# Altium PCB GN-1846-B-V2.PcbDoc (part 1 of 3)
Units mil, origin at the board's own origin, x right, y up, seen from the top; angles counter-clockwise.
Board outline 11621.85 x 2979.29 mil, 2 copper layers (Top, Bottom), stack 12.7 mil thick; 356 components, 252 nets, 1224 pads, 826 vias.
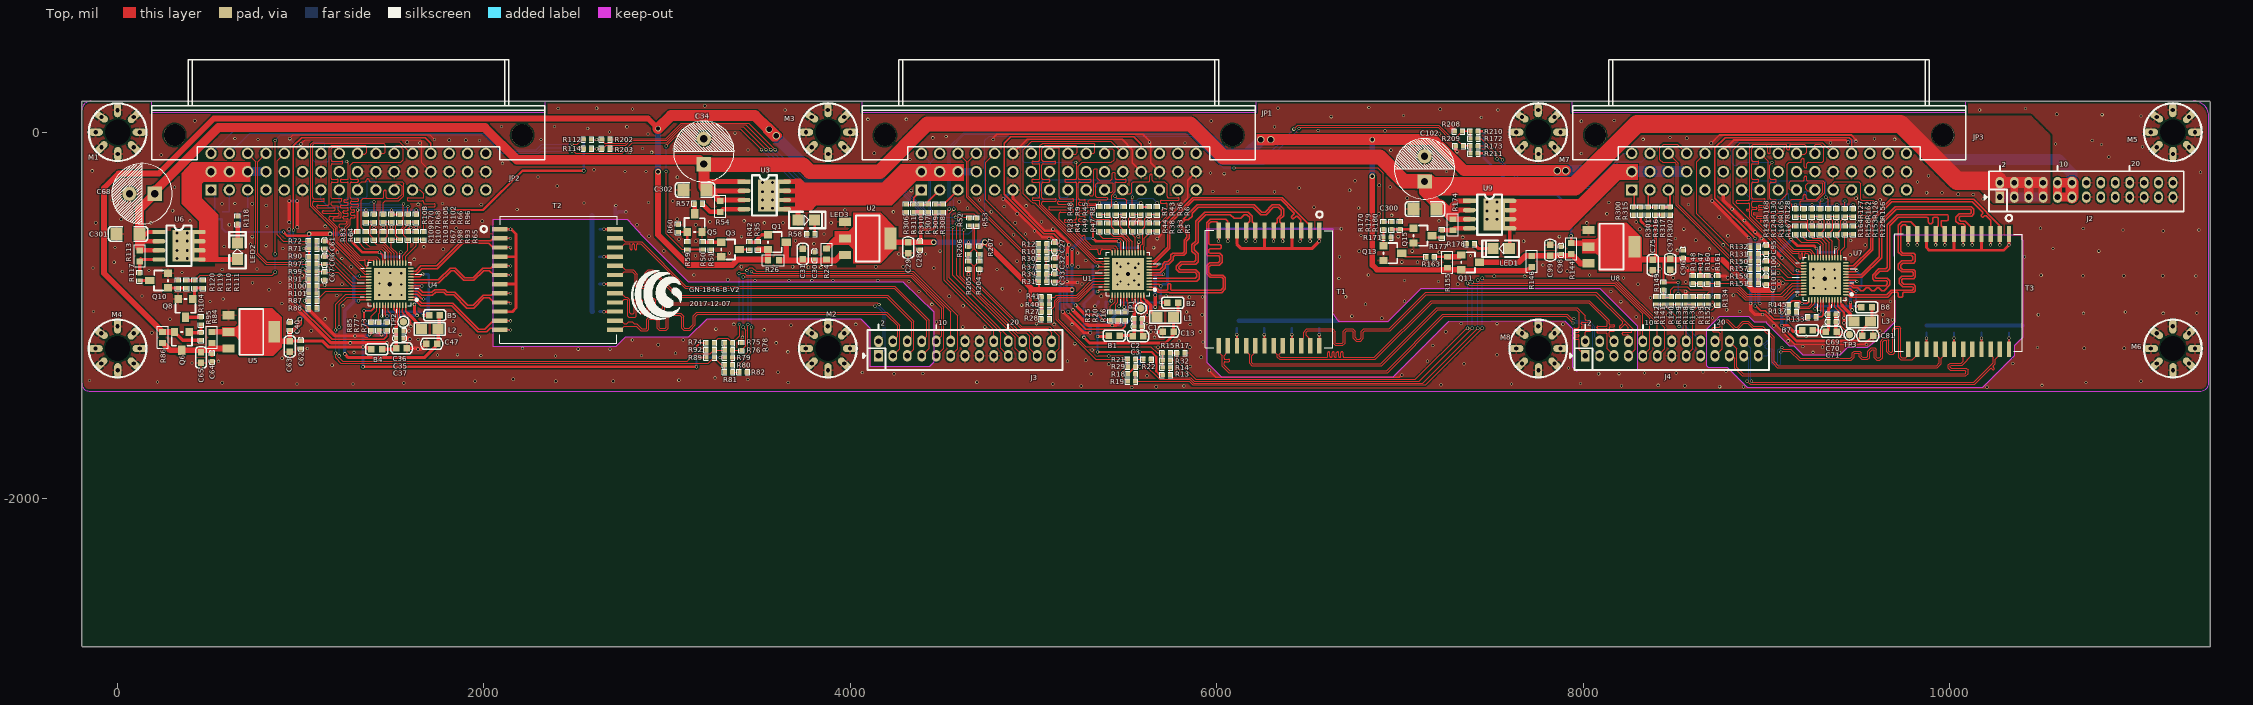
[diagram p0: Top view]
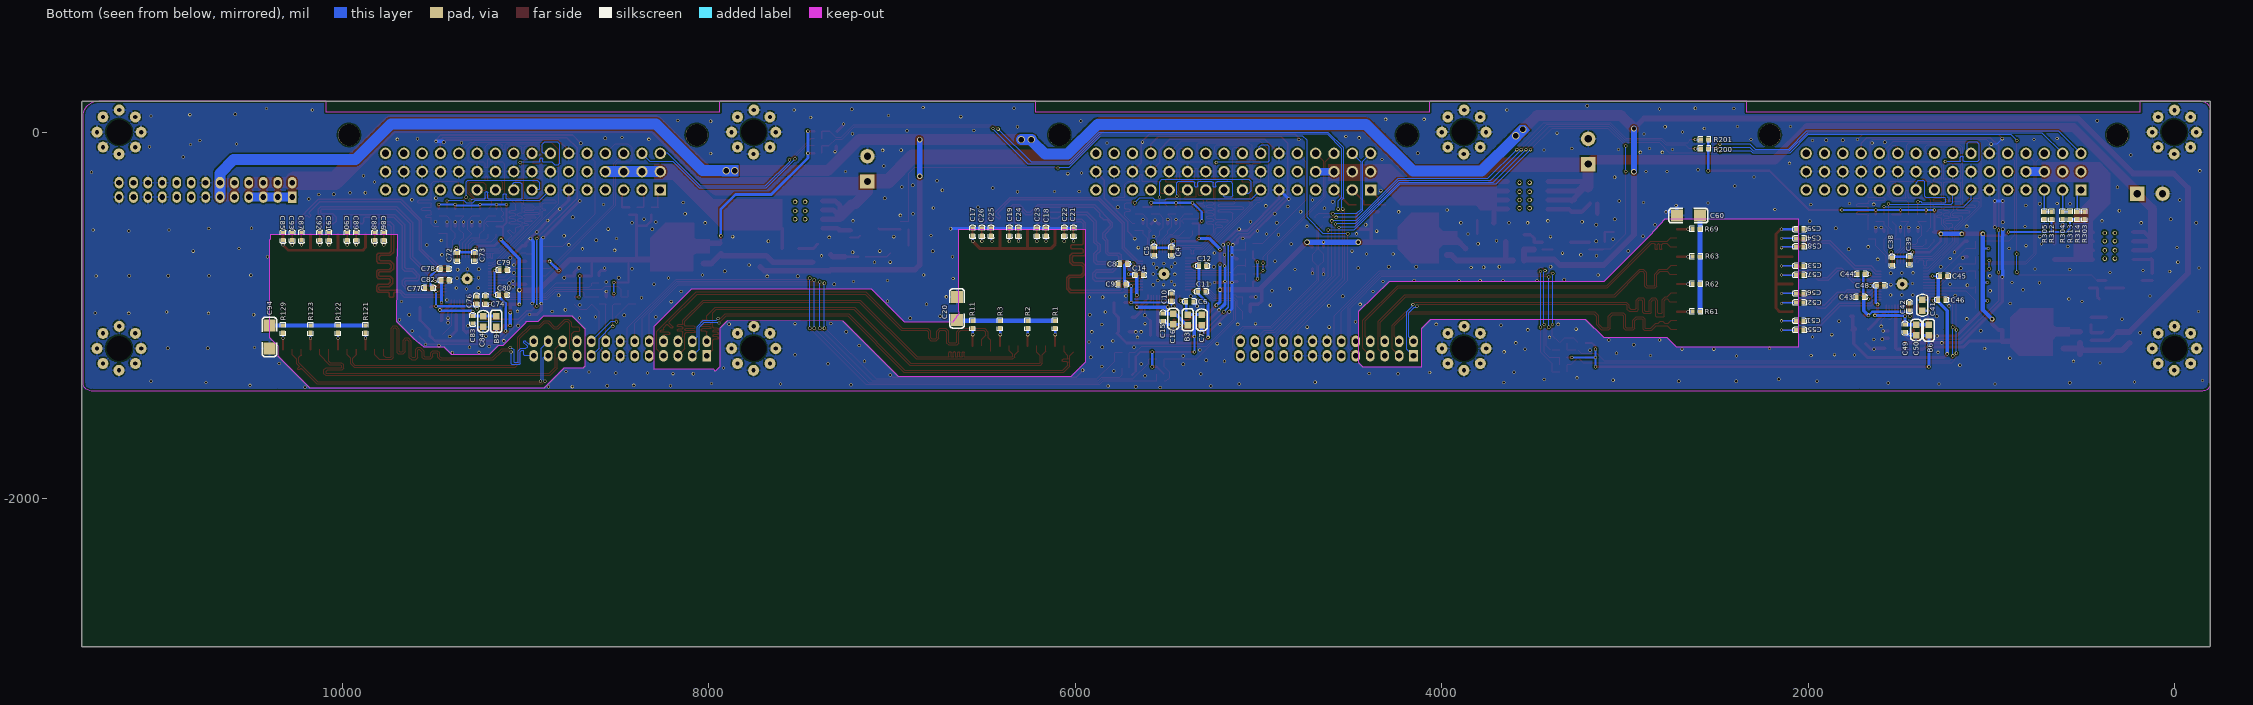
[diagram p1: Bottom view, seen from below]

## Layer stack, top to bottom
Top: signal copper 1.35
Dielectric: dielectric 10, FR-4, Dk 4.3
Bottom: signal copper 1.35

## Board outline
-196.85,167.44 -195,169.29 185,169.29 11420.71,169.29 11425,165 11425,65 11425,-2805 11425,-2810 -190.41,-2810 -196.85,-2803.55 -196.85,-2775 -196.85,167.44

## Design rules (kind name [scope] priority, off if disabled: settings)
Clearance "'Default' PADS rule_18" [All] p1: gap=5
ComponentClearance "'Default' PADS rule_12" [All] p1: gap=0 collisioncheckmode=3 verticalgap=0 showdistances=FALSE
FlightTimeFalling "'Default' PADS rule_10" [All] p1: maximum=10.00
FlightTimeRising "'Default' PADS rule_9" [All] p1: maximum=10.00
Length "'Default' PADS rule_5" [All] p1: maxlimit=50000 minlimit=0
MaxMinImpedance "'Default' PADS rule_8" [All] p1: minimum=50.00 maximum=150.0
MinimumSolderMaskSliver [All] p1: minsoldermaskwidth=0
PlaneClearance "'Default' PADS rule_14" [All] p1: clearance=5
PlaneConnect "Power Plane Connect Style - pads with no thermal_19" [(Name='U7-49')] p1: planeconnectstyle=NoConnect reliefexpansion=20 reliefentries=4 reliefconductorwidth=10 reliefairgap=10 // PAD - No Thermal Connect Rule
PlaneConnect "Power Plane Connect Style - pads with no thermal" [(Name='JP1-A14') Or (Name='JP1-A15') Or (Name='JP1-A16') Or (Name='JP1-B5') Or (Name='JP1-B6') Or (Name='JP1-C1') Or (Name='JP1-C2') Or (Name='JP1-C3') Or (Name='JP1-C4') Or (Name='JP1-C5') Or (Name='JP1-C13') Or (Name='JP1-C14') Or (Name='JP1-C15') Or (Name='JP1-C16') Or (Name='JP1-0') Or (Name='JP1-0/2') Or (Name='JP2-A14') Or (Name='JP2-A15') Or (Name='JP2-A16') Or (Name='JP2-B5') Or (Name='JP2-B6') Or (Name='JP2-C1') Or (Name='JP2-C2') Or (Name='JP2-C3') Or (Name='JP2-C4') Or (Name='JP2-C5') Or (Name='JP2-C13') Or (Name='JP2-C14') Or (Name='JP2-C15') Or (Name='JP2-C16') Or (Name='JP2-0') Or (Name='JP2-0/2') Or (Name='JP3-A14') Or (Name='JP3-A15') Or (Name='JP3-A16') Or (Name='JP3-B5') Or (Name='JP3-B6') Or (Name='JP3-C1') Or (Name='JP3-C2') Or (Name='JP3-C3') Or (Name='JP3-C4') Or (Name='JP3-C5') Or (Name='JP3-C13') Or (Name='JP3-C14') Or (Name='JP3-C15') Or (Name='JP3-C16') Or (Name='JP3-0') Or (Name='JP3-0/2') Or (Name='U1-49') Or (Name='U4-49')] p2: planeconnectstyle=NoConnect reliefexpansion=20 reliefentries=4 reliefconductorwidth=10 reliefairgap=10 // PAD - No Thermal Connect Rule
PlaneConnect "Power Plane Connect Style - from global settings" [All] p3: planeconnectstyle=Relief reliefexpansion=20 reliefentries=4 reliefconductorwidth=15 reliefairgap=10
PolygonConnect PolygonConnect_1 [All vs isvia] p1: connectstyle=Direct reliefconductorwidth=10 reliefentries=4 polygonreliefangle="90 Angle"
PolygonConnect [All] p2: connectstyle=Relief reliefconductorwidth=10 reliefentries=4 polygonreliefangle="90 Angle"
RoutingLayers "'Default' PADS rule_3" [All] p1: top layer_v5=TRUE bottom layer_v5=TRUE
RoutingPriority "'Default' PADS rule_2" [All] p1: routingpriority=3
RoutingTopology "'Default' PADS rule" [All] p1: topology=Shortest
RoutingVias "'Default' PADS rule_4" [All] p1: holewidth=12 width=18 viastyle="Through Hole" minholewidth=12 minwidth=18 maxholewidth=12 maxwidth=18
SMDToCorner "'Default' PADS rule_16" [All] p1: distance=0
SMDToPlane "'Default' PADS rule_17" [All] p1: distance=50000
SilkToSilkClearance [All] p1: silktosilkclearance=0
SilkscreenOverComponentPads [All] p1: minsilkscreentomaskgap=0
SolderMaskExpansion [All] p1: expansion=5
TestPointUsage FabricationTestPointUsage [All] p1: valid=0 allowmultiple=FALSE
Testpoint FabricationTestpoint [All] p1: side=3 testpointundercomponent=TRUE minsize=40 maxsize=100 preferedsize=60 minholesize=0 maxholesize=40 preferedholesize=32 testpointgrid=1 style=297 order=0123456789
Width "'Default' PADS rule_13" [All] p1: maxlimit=100 minlimit=5 preferedwidth=8
15 further rules are at their usual default settings.

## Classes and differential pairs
component class "P02 Block": M1 M2 M3 M4 M5 M6 M7 M8
component class "P05 PHY 3": B7 B8 B9 C69 C70 C71 C72 C73 C74 C75 C76 C77 C78 C79 C80 C81 C82 C83 C84 C85 C86 C87 C88 C89 C90 C91 C92 C93 C94 C95 C96 C97 C98 C99 C100 C101 C102 c300 JP3 L3 LED1 Q11 Q13 Q15 R121 R122 R123 R124 R125 R126 R127 R128 R129 R130 R131 R132 R133 R134 R135 R136 R137 R138 R139 R140 R141 R142 R143 R144 R145 R146 R147 R148 R149 R150 R151 R152 R153 R155 R156 R157 R158 R159 R160 R161 R162 R163 R164 R165 R167 R168 R169 R170 R171 R172 R173 R174 R177 R178 R179 R180 R208 R209 R210 R211 R300 R301 R302 R315 R316 R317 T3 TP3 U7 U8 U9
component class "P04 PHY 2": B4 B5 B6 C35 C36 C37 C38 C39 C40 C41 C42 C43 C44 C45 C46 C47 C48 C49 C50 C51 C52 C53 C54 C55 C56 C57 C58 C59 C60 C61 C62 C63 C64 C65 C66 C67 C68 c301 JP2 L2 LED2 Q6 Q8 Q10 R61 R62 R63 R64 R65 R66 R67 R68 R69 R70 R71 R72 R73 R74 R75 R76 R77 R78 R79 R80 R81 R82 R83 R84 R85 R86 R87 R88 R89 R90 R91 R92 R93 R95 R96 R97 R98 R99 R100 R101 R102 R103 R104 R105 R107 R108 R109 R110 R111 R112 R113 R114 R117 R118 R119 R120 R200 R201 R202 R203 R303 R304 R305 R312 R313 R314 T2 TP2 U4 U5 U6
component class "P03 PHY 1": B1 B2 B3 C1 C2 C3 C4 C5 C6 C7 C8 C9 C10 C11 C12 C13 C14 C15 C16 C17 C18 C19 C20 C21 C22 C23 C24 C25 C26 C27 C28 C29 C30 C31 C32 C33 C34 c302 JP1 L1 LED3 Q1 Q3 Q5 R1 R2 R3 R4 R5 R6 R7 R8 R9 R10 R11 R12 R13 R14 R15 R16 R17 R18 R19 R20 R21 R22 R23 R24 R25 R26 R27 R28 R29 R30 R31 R32 R33 R35 R36 R37 R38 R39 R40 R41 R42 R43 R44 R45 R47 R48 R49 R50 R51 R52 R53 R54 R57 R58 R59 R60 R204 R205 R206 R207 R306 R307 R308 R309 R310 R311 T1 TP1 U1 U2 U3
component class "P06 CONNECT & LED": J2 J3 J4

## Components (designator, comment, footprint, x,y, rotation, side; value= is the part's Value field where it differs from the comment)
B1 "MGLB1608M600T3R0-LF" L0603 5440,-1110 r270 top
B2 "MGLB1608M600T3R0-LF" L0603 5760,-930 r90 top
B3 "MGLB1608M600T3R0-LF" L0603 5385,-1025 r0 bottom
B4 "MGLB1608M600T3R0-LF" L0603 1415,-1185 r270 top
B5 "MGLB1608M600T3R0-LF" L0603 1730,-1000 r90 top
B6 "MGLB1608M600T3R0-LF" L0603 1340,-1080 r180 bottom
B7 "MGLB1608M600T3R0-LF" L0603 9225,-1080 r270 top
B8 "MGLB1608M600T3R0-LF" L0603 9548,-956 r90 top
B9 "MGLB1608M600T3R0-LF" L0603 9161,-1033 r180 bottom
C1 "0.1uF" 0402C 5550.47,-1020 r0 top
C2 "0.1uF" 0402C 5550.47,-1060 r0 top
C3 "10uF" C0603 5570,-1115 r0 top
C4 "0.1uF" 0402C 5475,-630.47 r270 bottom
C5 "0.1uF" 0402C 5570,-630 r270 bottom
C6 "0.1uF" 0402C 5395,-925 r180 bottom
C7 "10uF" C0603 5310,-1025 r270 bottom
C8 "0.1uF" 0402C 5716.74,-718.26 r0 bottom
C9 "0.1uF" 0402C 5725,-830 r0 bottom
C10 "0.1uF" 0402C 5475,-920 r90 bottom
C11 "0.1uF" 0402C 5330,-870 r180 bottom
C12 "0.1uF" 0402C 5325,-730 r180 bottom
C13 "10uF" C0603 5735,-1090 r180 top
C14 "0.1uF" 0402C 5670,-780 r180 bottom
C15 "0.1uF" 0402C 5520,-990.47 r270 bottom
C16 "10uF" C0603 5465,-1020 r270 bottom
C17 "0.1uF" 0402C 6560,-565 r90 bottom
C18 "nc" 0402C 6160,-525 r270 bottom
C19 "nc" 0402C 6360,-525 r270 bottom
C20 "1000pF/1KV" C1206 6645,-1025 r90 bottom
C21 "nc" 0402C 6010,-525 r270 bottom
C22 "nc" 0402C 6060,-525 r270 bottom
C23 "nc" 0402C 6210,-525 r270 bottom
C24 "nc" 0402C 6310,-525 r270 bottom
C25 "nc" 0402C 6460,-525 r270 bottom
C26 "nc" 0402C 6510,-525 r270 bottom
C27 "0.1uF" 0402C 5115,-605 r270 top
C28 "0.1uF" 0402C 4380,-599.53 r270 top
C29 "10uF" C0603 4315,-630 r270 top
C30 "0.1uF" 0402C 3805,-695 r90 top
C31 "10uF" C0603 3740,-665 r90 top
C32 "nc" 0402C 5115,-690 r270 top
C33 "nc" 0402C 5115,-815 r90 top
C34 "220uF/25V/DIP" CE8X3.5 3200,-105 r90 top
C35 "0.1uF" 0402C 1520,-1125 r0 top
C36 "0.1uF" 0402C 1520,-1085 r0 top
C37 "10uF" C0603 1550,-1180 r0 top
C38 "0.1uF" 0402C 1540.92,-685 r270 bottom
C39 "0.1uF" 0402C 1446.43,-680 r270 bottom
C40 "0.1uF" 0402C 940,-1080 r90 top
C41 "10uF" C0603 1375,-945 r90 bottom
C42 "0.1uF" 0402C 1446.43,-973.7 r90 bottom
C43 "0.1uF" 0402C 1695,-900 r0 bottom
C44 "0.1uF" 0402C 1690,-775 r0 bottom
C45 "0.1uF" 0402C 1279.76,-784.76 r180 bottom
C46 "0.1uF" 0402C 1290,-915 r180 bottom
C47 "10uF" C0603 1715,-1155 r180 top
C48 "0.1uF" 0402C 1625,-837.08 r180 bottom
C49 "0.1uF" 0402C 1470,-1050.47 r270 bottom
C50 "10uF" C0603 1410,-1080 r270 bottom
C51 "nc" 0402C 2025,-1030 r0 bottom
C52 "nc" 0402C 2025,-930 r0 bottom
C53 "nc" 0402C 2025,-730 r0 bottom
C54 "nc" 0402C 2025,-580 r0 bottom
C55 "nc" 0402C 2025,-1080 r0 bottom
C56 "nc" 0402C 2025,-880 r0 bottom
C57 "nc" 0402C 2025,-780 r0 bottom
C58 "nc" 0402C 2025,-625 r0 bottom
C59 "0.1uF" 0402C 2065,-530 r180 bottom
C60 "1000pF/1KV" C1206 2590,-455 r0 bottom
C61 "0.1uF" 0402C 1130,-595 r270 top
C62 "0.1uF" 0402C 1000,-1140 r270 top
C63 "10uF" C0603 940,-1170 r270 top
C64 "0.1uF" 0402C 515,-1210 r270 top
C65 "10uF" C0603 455,-1230 r270 top
C66 "nc" 0402C 1130,-680 r270 top
C67 "nc" 0402C 1130,-805 r90 top
C68 "220uF/25V/DIP" CE8X3.5 133.1,-335.8 r180 top
C69 "0.1uF" 0402C 9340,-995 r0 top
C70 "0.1uF" 0402C 9340,-1035 r0 top
C71 "10uF" C0603 9355,-1090 r0 top
C72 "0.1uF" 0402C 9375,-660 r270 bottom
C73 "0.1uF" 0402C 9280.67,-660 r270 bottom
C74 "0.1uF" 0402C 9220,-936 r90 bottom
C75 "10uF" C0603 8380,-725 r270 top
C76 "0.1uF" 0402C 9268,-937 r90 bottom
C77 "0.1uF" 0402C 9510.35,-849.65 r0 bottom
C78 "0.1uF" 0402C 9464.49,-745.51 r180 bottom
C79 "0.1uF" 0402C 9144,-752 r180 bottom
C80 "0.1uF" 0402C 9147,-888 r180 bottom
C81 "10uF" C0603 9554,-1111 r0 top
C82 "0.1uF" 0402C 9461,-808.5 r180 bottom
C83 "0.1uF" 0402C 9290,-1004 r270 bottom
C84 "10uF" C0603 9233,-1033 r270 bottom
C85 "0.1uF" 0402C 10325,-590 r90 bottom
C86 "nc" 0402C 9775,-550 r270 bottom
C87 "nc" 0402C 10225,-550 r270 bottom
C88 "nc" 0402C 9825,-550 r270 bottom
C89 "nc" 0402C 9925,-550 r270 bottom
C90 "nc" 0402C 9975,-550 r270 bottom
C91 "nc" 0402C 10075,-550 r270 bottom
C92 "nc" 0402C 10125,-550 r270 bottom
C93 "nc" 0402C 10275,-550 r270 bottom
C94 "1000pF/1KV" C1206 10400,-1055 r270 bottom
C95 "0.1uF" 0402C 9000,-620 r270 top
C96 "0.1uF" 0402C 8545,-685 r90 top
C97 "10uF" C0603 8475,-720 r270 top
C98 "0.1uF" 0402C 7880,-665 r90 top
C99 "10uF" C0603 7820,-645 r90 top
C100 "nc" 0402C 9000,-705 r270 top
C101 "nc" 0402C 9000,-830 r90 top
C102 "220uF/25V/DIP" CE8X3.5 7135,-200 r90 top
C300 "10uF" c1206 7200,-420 r180 top (schematic designator c300)
C301 "10uF" c1206 120,-555 r180 top (schematic designator c301)
C302 "10uF" c1206 3215,-315 r180 top (schematic designator c302)
J2 "CON14" HERDER13X2-2.0 10275.59,-354.33 r0 top locked
J3 "CON14" HERDER13X2-2.0 4153.54,-1220.47 r0 top locked
J4 "CON14" HERDER13X2-2.0 8011.81,-1220.47 r0 top locked
JP1 "3348RFRS-029" 3348RFRS-029 5137.8,-215.35 r180 top locked
JP2 "3348RFRS-029" 3348RFRS-029 1259.84,-215.35 r180 top locked
JP3 "3348RFRS-029" 3348RFRS-029 9015.75,-215.35 r180 top locked
L1 "CBC3225T4R7MR" FB0805 5765,-1010 r180 top
L2 "CBC3225T4R7MR" FB0805 1750,-1075 r180 top
L3 "CBC3225T4R7MR" FB0805 9570,-1034 r180 top
LED1 "GRE/0805" LED0805 7510,-635 r0 top
LED2 "GRE/0805" LED0805 655,-605 r270 top
LED3 "GRE/0805" LED0805 3805,-480 r180 top
M1 "HOLE-8STARS" HK 0.47,-0.28 r0 top locked
M2 "HOLE-8STARS" HK 3877.95,-1181.1 r0 top locked
M3 "HOLE-8STARS" HK 3878.43,0 r0 top locked
M4 "HOLE-8STARS" HK 0,-1181.1 r0 top locked
M5 "HOLE-8STARS" HK 11220.47,0 r0 top locked
M6 "HOLE-8STARS" HK 11220.47,-1181.1 r0 top locked
M7 "HOLE-8STARS" HK 7755.91,0 r0 top locked
M8 "HOLE-8STARS" HK 7755.91,-1181.1 r0 top locked
Q1 "P6403FMG" SOT23 3600,-600 r270 top
Q3 "MMBT3904" SOT23 3345,-640 r270 top
Q5 "MMBT3904" SOT23 3150,-495 r0 top
Q6 "P6403FMG" SOT23 350,-1140 r180 top
Q8 "MMBT3904" SOT23 370,-960 r180 top
Q10 "MMBT3904" SOT23 225,-810 r90 top
Q11 "P6403FMG" SOT23 7385,-710 r270 top
Q13 "MMBT3904" SOT23 6960,-660 r270 top
Q15 "MMBT3904" SOT23 7125,-565 r270 top
R1 "75" 0402R 6110,-1070 r90 bottom
R2 "75" 0402R 6260,-1070 r90 bottom
R3 "75" 0402R 6410,-1070 r90 bottom
R4 "33" 0402R 5405,-499 r270 top
R5 "33" 0402R 5675,-499 r270 top
R6 "33" 0402R 5675,-409 r270 top
R7 "33" 0402R 5540,-409 r270 top
R8 "33" 0402R 5495,-409 r270 top
R9 "33" 0402R 5405,-409 r270 top
R10 "nc" 0402R 5030,-650 r0 top
R11 "75" 0402R 6560,-1070 r90 bottom
R12 "33" 0402R 5030,-610 r0 top
R13 "nc" 0402R 5705,-1325 r0 top
R14 "0" 0402R 5705,-1285 r0 top
R15 "nc" 0402R 5705,-1205 r0 top
R16 "33" 0402R 5500,-1025 r90 top
R17 "4.7K" 0402R 5825,-1205 r180 top
R18 "4.7K" 0402R 5515,-1320 r0 top
R19 "nc" 0402R 5515,-1360 r0 top
R20 "2.49K/1%" 0402R 5460,-1025 r90 top
R21 "0" 0402R 5515,-1240 r0 top
R22 "nc" 0402R 5640,-1240 r180 top
R23 "4.7K" 0402R 5360,-539 r90 top
R24 "nc" R0603 3870,-665 r270 top
R25 "4.7K" 0402R 5420,-985 r270 top
R26 "nc" R0603 3580,-700 r180 top
R27 "4.7K" 0402R 5085,-980 r180 top
R28 "nc" 0402R 5085,-1020 r180 top
R29 "4.7K" 0402R 5515,-1280 r0 top
R30 "1.5K" 0402R 5070,-690 r180 top
R31 "1.5K" 0402R 5070,-815 r180 top
R32 "4.7K" 0402R 5705,-1245 r0 top
R33 "4.7K" 0402R 5630,-539 r90 top
R35 "100K" 0402R 3495,-640 r90 top
R36 "4.7K" 0402R 5630,-449 r90 top
R37 "33" 0402R 5030,-735 r0 top
R38 "nc" 0402R 5585,-539 r90 top
R39 "33" 0402R 5030,-775 r0 top
R40 "4.7K" 0402R 5085,-940 r180 top
R41 "nc" 0402R 5085,-900 r180 top
R42 "10K" 0402R 3450,-600 r270 top
R43 "4.7K" 0402R 5585,-449 r90 top
R44 "nc" 0402R 5540,-539 r90 top
R45 "4.7K" 0402R 5450,-449 r90 top
R47 "nc" 0402R 5495,-539 r90 top
R48 "4.7K" 0402R 5360,-449 r90 top
R49 "nc" 0402R 5450,-539 r90 top
R50 "2K" 0402R 3195,-600 r270 top
R51 "1K" 0402R 3240,-640 r90 top
R52 "100" 0402R 4650,-470 r270 top
R53 "100" 0402R 4690,-470 r270 top
R54 "100K" R0603 3290,-405 r90 top
R57 "0" 0402R 3150,-390 r0 top
R58 "10K" 0402R 3765,-555 r0 top
R59 "2K" 0402R 3110,-600 r270 top
R60 "1K" 0402R 3060,-505 r270 top
R61 "75" 0402R 2630.8,-979.21 r180 bottom
R62 "75" 0402R 2630.8,-829.21 r180 bottom
R63 "75" 0402R 2630.8,-679.21 r180 bottom
R64 "33" 0402R 1355,-545 r270 top
R65 "33" 0402R 1670,-545 r270 top
R66 "33" 0402R 1585,-450 r270 top
R67 "33" 0402R 1540,-545 r270 top
R68 "33" 0402R 1450,-450 r270 top
R69 "75" 0402R 2630.8,-529.21 r180 bottom
R70 "33" 0402R 1400,-450 r270 top
R71 "nc" 0402R 1045,-635 r0 top
R72 "33" 0402R 1045,-595 r0 top
R73 "33" 0402R 1470,-1080 r90 top
R74 "nc" 0402R 3215,-1150 r0 top
R75 "0" 0402R 3315,-1150 r0 top
R76 "nc" 0402R 3315,-1190 r0 top
R77 "2.49K/1%" 0402R 1425,-1080 r90 top
R78 "4.7K" 0402R 3405,-1150 r270 top
R79 "4.7K" 0402R 3315,-1230 r0 top
R80 "nc" 0402R 3315,-1270 r0 top
R81 "0" 0402R 3315,-1310 r0 top
R82 "nc" 0402R 3435,-1310 r180 top
R83 "4.7K" 0402R 1310,-585 r90 top
R84 "nc" R0603 515,-1120 r270 top
R85 "4.7K" 0402R 1385,-1040 r270 top
R86 "nc" R0603 245,-1120 r90 top
R87 "4.7K" 0402R 1085,-920 r180 top
R88 "nc" 0402R 1085,-960 r180 top
R89 "4.7K" 0402R 3255,-1230 r180 top
R90 "1.5K" 0402R 1085,-680 r180 top
R91 "1.5K" 0402R 1085,-800 r180 top
R92 "4.7K" 0402R 3255,-1190 r180 top
R93 "4.7K" 0402R 1630,-585 r90 top
R95 "100K" 0402R 455,-1135 r90 top
R96 "4.7K" 0402R 1630,-490 r90 top
R97 "33" 0402R 1045,-720 r0 top
R98 "nc" 0402R 1585,-585 r90 top
R99 "33" 0402R 1045,-760 r0 top
R100 "4.7K" 0402R 1085,-840 r180 top
R101 "nc" 0402R 1085,-880 r180 top
R102 "4.7K" 0402R 1540,-490 r90 top
R103 "nc" 0402R 1495,-585 r90 top
R104 "10K" 0402R 455,-1050 r90 top
R105 "4.7K" 0402R 1495,-490 r90 top
R107 "nc" 0402R 1450,-585 r90 top
R108 "4.7K" 0402R 1355,-490 r90 top
R109 "nc" 0402R 1400,-585 r90 top
R110 "2K" 0402R 420,-850 r90 top
R111 "1K" 0402R 465,-810 r270 top
R112 "100" 0402R 2545,-40 r0 top
R113 "100K" R0603 120,-675 r90 top
R114 "100" 0402R 2545,-90 r0 top
R117 "0" 0402R 120,-810 r90 top
R118 "10K" 0402R 655,-460 r270 top
R119 "2K" 0402R 375,-850 r90 top
R120 "1K" 0402R 330,-810 r270 top
R121 "75" 0402R 9875,-1095 r90 bottom
R122 "75" 0402R 10025,-1095 r90 bottom
R123 "75" 0402R 10175,-1095 r90 bottom
R124 "33" 0402R 9205,-515 r270 top
R125 "33" 0402R 9475,-515 r270 top
R126 "33" 0402R 9430,-420 r270 top
R127 "33" 0402R 9340,-420 r270 top
R128 "33" 0402R 9295,-420 r270 top
R129 "75" 0402R 10325,-1095 r90 bottom
R130 "33" 0402R 9205,-420 r270 top
R131 "nc" 0402R 8915,-665 r0 top
R132 "33" 0402R 8915,-625 r0 top
R133 "33" 0402R 9230,-1008 r0 top
R134 "nc" 0402R 8735,-900 r270 top
R135 "0" 0402R 8640,-900 r270 top
R136 "nc" 0402R 8600,-900 r270 top
R137 "2.49K/1%" 0402R 9123,-982 r0 top
R138 "4.7K" 0402R 8560,-900 r270 top
R139 "4.7K" 0402R 8520,-900 r270 top
R140 "nc" 0402R 8480,-900 r270 top
R141 "0" 0402R 8440,-900 r270 top
R142 "nc" 0402R 8400,-900 r270 top
R143 "4.7K" 0402R 9160,-555 r90 top
R144 "nc" R0603 7935,-635 r270 top
R145 "4.7K" 0402R 9164,-943 r180 top
R146 "nc" R0603 7720,-705 r270 top
R147 "4.7K" 0402R 8640,-825 r90 top
R148 "nc" 0402R 8600,-825 r90 top
R149 "4.7K" 0402R 8440,-860 r90 top
R150 "1.5K" 0402R 8955,-705 r180 top
R151 "1.5K" 0402R 8955,-825 r180 top
R152 "4.7K" 0402R 8680,-900 r270 top
R153 "4.7K" 0402R 9430,-555 r90 top
R155 "100K" R0603 7260,-710 r90 top
R156 "4.7K" 0402R 9475,-460 r90 top
R157 "33" 0402R 8915,-745 r0 top
R158 "nc" 0402R 9385,-555 r90 top
R159 "33" 0402R 8915,-785 r0 top
R160 "4.7K" 0402R 8680,-825 r90 top
R161 "nc" 0402R 8735,-825 r90 top
R162 "4.7K" 0402R 9385,-460 r90 top
R163 "10K" 0402R 7185,-680 r180 top
R164 "nc" 0402R 9340,-555 r90 top
R165 "4.7K" 0402R 9250,-460 r90 top
R167 "nc" 0402R 9295,-555 r90 top
R168 "4.7K" 0402R 9160,-460 r90 top
R169 "nc" 0402R 9250,-555 r90 top
R170 "2K" 0402R 6910,-530 r90 top
R171 "1K" 0402R 6950,-575 r180 top
R172 "100" 0402R 7425,-35 r180 top
R173 "100" 0402R 7425,-75 r180 top
R174 "100K" R0603 7290,-505 r90 top
R177 "0" 0402R 7230,-575 r90 top
R178 "10K" 0402R 7365,-610 r0 top
R179 "2K" 0402R 6955,-530 r90 top
R180 "1K" 0402R 7000,-490 r270 top
R200 "5K1(NC)" 0402R 2585,-90 r180 bottom
R201 "5K1(NC)" 0402R 2585,-40 r180 bottom
R202 "5K1" 0402R 2645,-40 r0 top
R203 "5K1" 0402R 2645,-90 r0 top
R204 "5K1" 0402R 4705,-705 r270 top
R205 "5K1" 0402R 4645,-705 r270 top
R206 "5K1(NC)" 0402R 4645,-665 r90 top
R207 "5K1(NC)" 0402R 4705,-665 r90 top
R208 "5K1" 0402R 7340,5 r180 top
R209 "5K1" 0402R 7345,-75 r180 top
R210 "5K1(NC)" 0402R 7385,5 r0 top
R211 "5K1(NC)" 0402R 7385,-115 r0 top
R300 "nc" 0402R 8275,-410 r270 top
R301 "nc" 0402R 8355,-410 r270 top
R302 "nc" 0402R 8475,-410 r270 top
R303 "nc" 0402R 490,-435 r270 bottom
R304 "nc" 0402R 610,-435 r270 bottom
R305 "nc" 0402R 710,-435 r270 bottom
R306 "nc" 0402R 4305,-395 r270 top
R307 "nc" 0402R 4425,-395 r270 top
R308 "nc" 0402R 4505,-395 r270 top
R309 "10K/NC" 0402R 4465,-395 r270 top
R310 "10K/NC" 0402R 4385,-395 r270 top
R311 "10K/NC" 0402R 4345,-395 r270 top
R312 "10K" 0402R 670,-435 r270 bottom
R313 "10K" 0402R 570,-435 r270 bottom
R314 "10K" 0402R 530,-435 r270 bottom
R315 "10K" 0402R 8315,-410 r270 top
R316 "10K" 0402R 8395,-410 r270 top
R317 "10K" 0402R 8435,-410 r270 top
T1 "H5007-H" H5007-H 6285.79,-850.8 r180 top locked
T2 "H5007-H" H5007-H 2400.8,-804.21 r270 top
T3 "H5007-H" H5007-H 10050,-870 r180 top
TP1 "T POINT A" TP_G 5585.85,-960.85 r270 top
TP2 "T POINT A" TP_G 1560,-1035 r270 top
TP3 "T POINT A" TP_G 9455,-1105 r270 top
U1 "RTL8211D" QFN-48P-RTL8211 5515.8,-774.21 r90 top
U2 "AS1117-3.3" SOT223 4095,-580 r270 top
U3 "SI7139" POWERPAKSO8 3420,-270 r0 top
U4 "RTL8211D" QFN-48P-RTL8211 1485.8,-829.21 r90 top
U5 "AS1117-3.3" SOT223 730,-1090 r270 top
U6 "SI7139" POWERPAKSO8 225,-545 r0 top
U7 "RTL8211D" QFN-48P-RTL8211 9320,-800 r90 top
U8 "AS1117-3.3" SOT223 8155,-625 r270 top
U9 "SI7139" POWERPAKSO8 7380,-375 r0 top

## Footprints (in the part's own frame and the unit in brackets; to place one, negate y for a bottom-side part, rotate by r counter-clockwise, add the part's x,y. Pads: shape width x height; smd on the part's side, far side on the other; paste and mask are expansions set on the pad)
0402C [mil]
  rect 23x23 smd: 1(0,0) 2(40,0)
  silkscreen extent -18,-15 58,15
0402R [mil]
  rect 23x23 smd: 1(0,0) 2(40,0)
  silkscreen extent -15,-15 55,15
3348RFRS-029 [mil]
  round 118.11 hole 118.11: 0(948.82,-200) 0/2(-948.82,-200)
  round 62 hole 39.37: A1(750,-100) A2(650,-100) A3(550,-100) A4(450,-100) A5(350,-100) A6(250,-100) A7(150,-100) A8(50,-100) A9(-50,-100) A10(-150,-100) A11(-250,-100) A12(-350,-100) A13(-450,-100) A14(-550,-100) A15(-650,-100) A16(-750,-100) B1(750,0) B2(650,0) B3(550,0) B4(450,0) B5(350,0) B6(250,0) B7(150,0) B8(50,0) B9(-50,0) B10(-150,0) B11(-250,0) B12(-350,0) B13(-450,0) B14(-550,0) B15(-650,0) B16(-750,0) C2(650,100) C3(550,100) C4(450,100) C5(350,100) C6(250,100) C7(150,100) C8(50,100) C9(-50,100) C10(-150,100) C11(-250,100) C12(-350,100) C13(-450,100) C14(-550,100) C15(-650,100) C16(-750,100)
  rect 62x62 hole 39.37: C1(750,100)
  silkscreen extent -1073,-612 1073,-65
C0603 [mm]
  rect 0.9x0.9 smd: 1(-0.75,0) 2(0.75,0)
  Top pour cut-out: -0.381,0.508 0.381,0.508 0.381,-0.508 -0.381,-0.508 -0.381,0.508
  silkscreen extent -1.52,-0.76 1.53,0.76
C1206 [mil]
  rect 65x65 smd: 1(0,0) 2(126,0)
  silkscreen extent -44,-40 170,40
c1206 [mil]
  rect 65x65 smd: 1(0,0) 2(126,0)
  silkscreen extent -44,-40 170,40
CE8X3.5 [mm]
  rect 2x2 hole 1: 1(-1.75,0)
  round 2 hole 1: 2(1.75,0)
  silkscreen extent -4.2,-4.2 4.2,4.2
FB0805 [mil]
  rect 60x55 smd: 1(0,0) 2(92,0)
  silkscreen extent -39,-34 131,34
H5007-H [mm]
  rect 0.6x2.2 smd: 1(-6.985,-8) 2(-5.715,-8) 3(-4.445,-8) 4(-3.175,-8) 5(-1.905,-8) 6(-0.635,-8) 7(0.635,-8) 8(1.905,-8) 9(3.175,-8) 10(4.445,-8) 11(5.715,-8) 12(6.985,-8) 13(6.985,8) 14(5.715,8) 15(4.445,8) 16(3.175,8) 17(1.905,8) 18(0.635,8) 19(-0.635,8) 20(-1.905,8) 21(-3.175,8) 22(-4.445,8) 23(-5.715,8) 24(-6.985,8)
  silkscreen extent -8.8,-10.63 8.82,8.3
HERDER13X2-2.0 [mm]
  rect 1.2x1.6 hole 0.8: 1(0,0)
  oval 1.2x1.6 hole 0.8: 2(0,2) 3(2,0) 4(2,2) 5(4,0) 6(4,2) 7(6,0) 8(6,2) 9(8,0) 10(8,2) 11(10,0) 12(10,2) 13(12,0) 14(12,2) 15(14,0) 16(14,2) 17(16,0) 18(16,2) 19(18,0) 20(18,2) 21(20,0) 22(20,2) 23(22,0) 24(22,2) 25(24,0) 26(24,2)
  silkscreen extent -2.13,-1.98 25.5,4.32
HK [mm]
  round 3 / inner round 1.524 / far side round 1.524 hole 3.5: 1(-0.012,0.007)
  oval 2x1 / inner round 1.524 / far side round 1.524 hole 0.6: 2(3.063,0.007) 6(-3.062,0.007)
  oval 2x1 / inner round 1.524 / far side round 1.524 hole 0.6 rot 135: 3(2.238,-2.068)
  oval 1x2 / inner round 1.524 / far side round 1.524 hole 0.6: 4(0.013,-3.018) 8(-0.025,3.075)
  oval 2x1 / inner round 1.524 / far side round 1.524 hole 0.6 rot 45: 5(-2.262,-2.068) 9(2.238,2.107)
  oval 2x1 / inner round 1.524 / far side round 1.524 hole 0.6 rot 145: 7(-2.262,2.107)
  silkscreen extent -4.01,-3.99 3.99,4.01
L0603 [mm]
  rect 0.9x0.9 smd: 1(0,0.75) 2(0,-0.75)
  Top pour cut-out: -0.508,0.381 0.508,0.381 0.508,-0.381 -0.508,-0.381
  silkscreen extent -0.76,-1.52 0.76,1.52
LED0805 [mil]
  rect 60x60 smd: A(89.68,-0.39) K(-0.32,-0.39)
  silkscreen extent -60,-45 140,45
POWERPAKSO8 [mm]
  rect 1.8x0.61 smd: 1(0,0)
  oval 1.8x0.61 smd: 2(0,-1.27) 3(0,-2.54) 4(0,-3.81) 5(5.6,-3.81) 6(5.6,-2.54) 7(5.6,-1.27) 8(5.6,0)
  rect 3x4.425 smd: 9(3.425,-1.9)
  silkscreen extent 1.08,-4.69 4.52,0.9
QFN-48P-RTL8211 [mil]
  oval 8x30 smd mask+2: 1(-86.61,-114.96) 2(-70.87,-114.96) 3(-55.12,-114.96) 4(-39.37,-114.96) 5(-23.62,-114.96) 6(-7.87,-114.96) 7(7.87,-114.96) 8(23.62,-114.96) 9(39.37,-114.96) 10(55.12,-114.96) 11(70.87,-114.96) 12(86.61,-114.96) 25(86.61,114.96) 26(70.87,114.96) 27(55.12,114.96) 28(39.37,114.96) 29(23.62,114.96) 30(7.87,114.96) 31(-7.87,114.96) 32(-23.62,114.96) 33(-39.37,114.96) 34(-55.12,114.96) 35(-70.87,114.96) 36(-86.61,114.96)
  oval 30x8 smd mask+2: 13(114.96,-86.61) 14(114.96,-70.87) 15(114.96,-55.12) 16(114.96,-39.37) 17(114.96,-23.62) 18(114.96,-7.87) 19(114.96,7.87) 20(114.96,23.62) 21(114.96,39.37) 22(114.96,55.12) 23(114.96,70.87) 24(114.96,86.61) 37(-114.96,86.61) 38(-114.96,70.87) 39(-114.96,55.12) 40(-114.96,39.37) 41(-114.96,23.62) 42(-114.96,7.87) 43(-114.96,-7.87) 44(-114.96,-23.62) 45(-114.96,-39.37) 46(-114.96,-55.12) 47(-114.96,-70.87) 48(-114.96,-86.61)
  rect 175x175 / inner round 60 / far side round 60 hole 23.62: 49(0,0)
  silkscreen extent -177,-177 177,179
R0603 [mil]
  rect 32x36 smd: 1(-30,0) 2(30,0)
  Top pour cut-out: -15,20 15,20 15,-20 -15,-20 -15,20
  silkscreen extent -60,-30 60,30
SOT23 [mil]
  rect 40x45 smd: 1(-40,-50) 2(40,-50)
  rect 40x50 smd: 3(0,50)
  silkscreen extent -55,-50 55,26
SOT223 [mil]
  rect 45x65 smd: 1(-91,-125) 2(0,-125) 3(91,-125)
  rect 118x65 smd: 4(0,125)
  silkscreen extent -125,-65 125,65
TP_G [mil]
  round 40 smd: 1(0,0)
  silkscreen extent -30,-30 30,30

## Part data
B1 B2 B3 B4 B5 B6 B7 B8 B9 L1 L2 L3: library part "CHOKE TORROID_0"
C1 C2 C3 C4 C5 C6 C7 C8 C9 C10 C11 C12 C13 C14 C15 C16 C17 C18 C19 C20 C21 C22 C23 C24 C25 C26 C27 C28 C29 C30 C31 C32 C33 C35 C36 C37 C38 C39 C40 C41 C42 C43 C44 C45 C46 C47 C48 C49 C50 C51 C52 C53 C54 C55 C56 C57 C58 C59 C60 C61 C62 C63 C64 C65 C66 C67 C69 C70 C71 C72 C73 C74 C75 C76 C77 C78 C79 C80 C81 C82 C83 C84 C85 C86 C87 C88 C89 C90 C91 C92 C93 C94 C95 C96 C97 C98 C99 C100 C101 C300 C301 C302: library part "CAP NP"
C34 C68 C102: library part "CAP POL"
LED1: library part LED_2
LED2: library part LED_3
LED3: library part LED_4
M1 M2 M3 M4 M5 M6 M7 M8: library part GEN35
Q1 Q6 Q11: library part "MOSFET P_0"
Q3 Q5 Q8 Q10 Q13 Q15: library part 2N3904
R1 R2 R3 R4 R5 R6 R7 R8 R9 R10 R11 R12 R13 R14 R15 R16 R17 R18 R19 R20 R21 R22 R23 R25 R27 R28 R29 R30 R31 R32 R33 R36 R37 R38 R39 R40 R41 R43 R44 R45 R47 R48 R49 R54 R57 R58 R59 R60 R61 R62 R63 R64 R65 R66 R67 R68 R69 R70 R71 R72 R73 R74 R75 R76 R77 R78 R79 R80 R81 R82 R83 R85 R87 R88 R89 R90 R91 R92 R93 R96 R97 R98 R99 R100 R101 R102 R103 R105 R107 R108 R109 R113 R117 R118 R119 R120 R121 R122 R123 R124 R125 R126 R127 R128 R129 R130 R131 R132 R133 R134 R135 R136 R137 R138 R139 R140 R141 R142 R143 R145 R147 R148 R149 R150 R151 R152 R153 R156 R157 R158 R159 R160 R161 R162 R164 R165 R167 R168 R169 R174 R177 R179 R180 R300 R301 R302 R303 R304 R305 R306 R307 R308 R309 R310 R311 R312 R313 R314 R315 R316 R317: library part R_0
R24 R26 R35 R42 R50 R51 R84 R86 R95 R104 R110 R111 R144 R146 R155 R163 R170 R171: library part R
R52 R53 R112 R114 R172 R173 R200 R201 R202 R203 R204 R205 R206 R207 R208 R209 R210 R211: library part R_1_Dup1
R178: library part R_1
T1 T2 T3: library part "PULSE H5007_0"
U1 U4 U7: library part RTL8211D_0
U2 U5 U8: library part AS1117-X_1

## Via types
v1: diameter 18, hole 12, Top to Bottom, 786 vias
v2: diameter 24, hole 16, Top to Bottom, 28 vias
v3: diameter 30, hole 20, Top to Bottom, 6 vias
v4: diameter 40, hole 30, Top to Bottom, 6 vias

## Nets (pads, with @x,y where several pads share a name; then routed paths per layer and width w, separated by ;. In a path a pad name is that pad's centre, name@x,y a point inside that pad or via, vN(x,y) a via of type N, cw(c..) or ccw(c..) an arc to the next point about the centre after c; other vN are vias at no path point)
5V0: J2.9 J2.10 J2.11 J2.12 Q1.2 Q6.2 Q11.2 R26.2 R35.1 R86.2 R95.1 R146.2 R155.1 | length 16035.6
  Top w18: Q6.2@310,-1090 355,-1135 R95.1@455,-1135
  Top w30: v3(6850,-240) 6850,-725 6875,-750 7260,-750 Q11.2@7335,-750 7341,-756 7699,-756 R146.2@7720,-735
  Top w32: Q6.2@310,-1090 R86.2@245,-1090 -75,-770 -75,-305 5,-225 224.95,-225 524.95,75 2895,75 v3(2950,20) ; v3(2950,-215) 2950,-560 3115,-725 3355,-725 3385,-695 3545,-695 R26.2@3550,-700 Q1.2@3550,-640 R35.1@3495,-640
  Top w50: J2.11@10669.29,-354.33 J2.9@10590.55,-354.33 J2.10@10590.55,-275.59 J2.12@10669.29,-275.59
  Top w60: v3(2950,20) 3020,90 3480,90 v4@3547.5,22.5 ; v4(6295,-40) v3(6850,-40) 7180,-40 7350,-210 v4(7860,-210) v4(7905,-210)
  Top w70: J2.11@10669.29,-354.33 J2.12@10669.29,-275.59
  Bottom w30: v3(6850,-240) v3(6850,-40)
  Bottom w32: v3(2950,-215) v3(2950,20)
  Bottom w60: v4@3592.5,-22.5 3782.5,-212.5 4157.5,-212.5 4413,43 5879.18,43 6042.18,-120 6165,-120 v4@6235,-50 ; v4(6240,-40) v4(6295,-40) ; v4@7915,-210 8035,-210 8290,45 9735,45 9930,-150 10595,-150 10669.29,-224.29 J2.12@10669.29,-275.59 J2.11@10669.29,-354.33
  other v4: 3595,-20 3556,15
12VIN: C34.1 C68.1 C102.1 C300.1 C301.1 C302.1 J2.1 J2.2 J2.3 J2.4 J2.5 J2.6 J2.7 J2.8 R54.2 R113.2 R174.2 U3.1 U3.2 U3.3 U6.1 U6.2 U6.3 U9.1 U9.2 U9.3 | length 13803.8
  Top w24: 120,-625 120,-640 122.5,-642.5 125,-645 U6.3@225,-645 ; 120,-620 145,-595 U6.2@225,-595 ; 120,-590 137.5,-572.5 165,-545 U6.1@225,-545
  Top w28: 3195,-280 3200,-285 3222.5,-307.5 R54.2@3285,-370 ; R54.2@3275,-370 R54.2@3285,-370 ; R54.2@3290,-375 R54.2@3285,-370 ; U3.3@3420,-370 3290,-370 R54.2@3285,-370 ; U3.2@3420,-320 3261.1,-320 3235.55,-294.45 3211.1,-270 3215,-270 U3.1@3420,-270 ; R174.2@7285,-475 R174.2@7290,-475 U9.3@7380,-475 ; R174.2@7285,-460 7320,-425 U9.2@7380,-425 ; 7285,-450 7285,-400 7310,-375 U9.1@7380,-375
  Top w35: 113.9,-625 120,-625
  Top w40: J2.3@10354.33,-354.33 J2.4@10354.33,-275.59
  Top w50: 120,-625 120,-620 120,-590 C301.1@120,-555 120,-417.8 C68.1@201.99,-335.8 201.99,-315 210,-315 550,25 2005,25 2180,-150 3176.1,-150 C34.1@3200,-173.9 C34.1@3204.1,-178 ; J2.1@10275.59,-354.33 J2.2@10275.59,-275.59 ; J2.5@10433.07,-354.33 J2.6@10433.07,-275.59 ; J2.7@10511.81,-354.33 J2.8@10511.81,-275.59
  Top w60: C302.1@3200,-300 3200,-285 C34.1@3200,-173.9 ; C102.1@7135,-268.9 7135,-325 C300.1@7200,-390 ; C300.1@7222.5,-397.5 R174.2@7285,-460 ; J2.2@10275.59,-275.59 J2.4@10354.33,-275.59 J2.6@10433.07,-275.59 J2.8@10511.81,-275.59
  Top w80: C34.1@3204.1,-178 3743,-178 3780,-215 4160,-215 4420,45 5855,45 6035,-135 6890,-135 7021.95,-266.95 7135,-266.95 7156.95,-266.95 7185,-295 7190,-300 ; J2.2@10265,-265 J2.2@10275.59,-275.59
  Top w100: C102.1@7163.05,-295 7185,-295 7955,-295 8295,45 9732.22,45 10042.22,-265 J2.2@10265,-265
  Bottom w50: J2.1@10275.59,-354.33 J2.3@10354.33,-354.33 J2.5@10433.07,-354.33 J2.7@10511.81,-354.33
A3V3A: B3.1 C14.1 C15.1 C16.1 U1.6 U1.41 | length 732.6
  Top w8: U1.41@5492.18,-889.17 5492.18,-947.18 5497.5,-952.5 v1@5500,-955 ; U1.6@5630.76,-782.08 5707.92,-782.08 5712.5,-777.5 v1@5715,-775
  Top w18: v1(5665,-955) v1(5665,-890)
  Bottom w8: C14.1@5670,-780 C14.1@5675,-775
  Bottom w12: C14.1@5675,-775 v1(5710,-775)
  Bottom w18: B3.1@5385,-1054.53 5390.47,-1054.53 5454.53,-990.47 C16.1@5465,-990.47 5515,-990.47 5500,-975.47 5500,-955 v1(5665,-955) ; v1(5665,-890) C14.1@5665,-783.88
  other v1: 5495,-955
A3V3D: B1.2 B3.2 C4.1 C5.1 C6.1 C7.1 C28.1 C29.1 R10.1 R13.1 R18.1 R23.2 R24.1 R25.2 R27.2 R29.2 R30.2 R31.2 R36.2 R40.2 R43.2 R45.2 R48.2 R206.2 R207.2 R309.2 R310.2 R311.2 U1.15 U1.21 U1.37 U2.2 U2.4 | length 4946.4
  Top w8: v1@5429.19,-915.81 U1.37@5429.19,-889.17 U1.37@5429.19,-900.81 ; v1(5465,-595) 5476.43,-606.43 U1.21@5476.43,-659.25 ; R18.1@5515,-1320 R29.2@5555,-1280 ; U1.15@5570.92,-659.25 5570.92,-609.08 5577.5,-602.5 v1@5580,-600
  Top w12: v1(5005,-800) 5020,-815 R31.2@5030,-815 5030,-855 ; v1(5005,-710) 5025,-690 R30.2@5030,-690 R10.1@5030,-650 ; v1(5310,-485) 5325,-500 ; v1(5325,-580) 5325,-500 ; v1(5350,-1200) v1(5580,-1200) 5645,-1200 5670,-1225 5670,-1305 5690,-1325 ; v1(5350,-995) 5380,-1025 R25.2@5420,-1025 ; R23.2@5360,-499 5326,-499 5325,-500 ; R48.2@5360,-409 v1(5360,-385) ; R45.2@5450,-409 v1(5450,-385) ; R29.2@5555,-1280 v1(5580,-1280) ; v1(5585,-385) R43.2@5585,-409 R36.2@5630,-409
  Top w15: v1(5325,-580) 5340,-595 v1(5465,-595)
  Top w18: R311.2@4345,-435 R310.2@4385,-435 ; C28.1@4380,-599.53 4385,-594.53 4385,-530 ; R310.2@4385,-445 4385,-530 ; R309.2@4465,-445 4465,-515 4450,-530 4385,-530 ; R206.2@4645,-625 v1(4645,-600) ; R207.2@4705,-625 4710,-625 v3(4735,-600) ; 4982.57,-847.57 4982.57,-922.57 5000,-940 R40.2@5045,-940 R27.2@5045,-980 ; v1(5210,-725) v1(5210,-640) ; v1(5230,-945) 5280,-995 v1(5350,-995) ; v1(5350,-1115) 5405.47,-1115 B1.2@5410.47,-1110
  Top w30: 4125,-610 4135,-600 4220,-600 C29.1@4315,-600 ; C29.1@4315,-599.53 C28.1@4380,-599.53 4454.53,-599.53 v3(4455,-600) ; v3(4735,-600) 4982.57,-847.57 4995,-860 v2(5210,-860)
  Top w32: R24.1@3870,-635 3920,-585 3945,-585 U2.2@3955,-595
  Bottom w8: C6.1@5395,-925 5420,-925 v1(5425,-920)
  Bottom w12: v1(5005,-800) v1(5005,-710) ; v1(5310,-485) 5310,-435 v1(5360,-385) v1(5450,-385) v1(5585,-385) ; v1(5350,-1200) v1(5350,-1115) ; v1(5465,-595) 5465,-620.47 C4.1@5475,-630.47 ; C5.1@5570,-630.47 5570,-610 v1@5577.5,-602.5 ; v1(5580,-1280) v1(5580,-1200)
  Bottom w15: C7.1@5310,-995.47 v1@5350,-995.47 ; v1(5350,-995) v1@5350,-995.47 ; C6.1@5395,-925 5395,-985.47 B3.2@5385,-995.47 v1@5350,-995.47 ; C4.1@5475,-630.47 C5.1@5570,-630.47
  Bottom w18: v1(5210,-725) v2(5210,-860) 5210,-925 v1(5230,-945) ; v1(5210,-640) 5270,-580 v1@5320,-580 ; v1(5350,-1115) v1@5350,-995.47
  Bottom w30: v3(4455,-600) v1(4645,-600) v3(4735,-600)
  other v1: 5575,-600
A5V: C30.1 C31.1 Q1.3 R24.2 R26.1 U2.3 | length 474.9
  Top w32: R26.1@3611,-701 3644,-701 ; Q1.3@3650,-600 3650,-695 3644,-701 ; U2.3@3970,-671 3946,-671 3916,-701 3870,-701 3740,-701 3644,-701
A_MCLK: JP1.A3 R37.1 | length 843.8
  Top w5: JP1.A3@4587.8,-115.35 4635,-162.56 4635,-354.14 4950,-669.14 4950,-725 4960,-735 R37.1@5030,-735
A_MDIO: JP1.A4 R39.1 | length 857.3
  Top w5: JP1.A4@4687.8,-115.35 4645,-158.15 4645,-350 4975,-680 v1(4975,-715) ; v1(4975,-755) 4995,-775 R39.1@5030,-775
  Bottom w5: v1(4975,-755) v1(4975,-715)
A_MX1_N: J4.7 T1.22 | length 2467.5
  Top w6: T1.22@6460.79,-1195.79 T1.22@6460.79,-1165.76 6460.79,-1136.21 6474,-1123 6474,-1092 6492.72,-1073.28 6632.83,-1073.28 6648,-1088.44 6648,-1148.44 6652.56,-1153 6684.44,-1153 6690,-1147.44 6690,-1087.44 6704.17,-1073.28 6743.83,-1073.28 6757,-1086.44 6757,-1120.56 6765.44,-1129 6781,-1129 6789,-1121 6789,-1087.44 6803.17,-1073.28 6941.72,-1073.28 7140,-875 8072,-875 8284,-1087 8284,-1184.5 J4.7@8248.03,-1220.47
A_MX1_P: J4.8 T1.23 | length 2451.5
  Top w6: T1.23@6510.79,-1165.76 6510.79,-1130.79 6488.28,-1108.28 6488.28,-1093.28 6497.28,-1084.28 6628.28,-1084.28 6637,-1093 6637,-1153 6648,-1164 6689,-1164 6701,-1152 6701,-1092 6708.72,-1084.28 6739.28,-1084.28 6746,-1091 6746,-1125.11 6760.89,-1140 6785.56,-1140 6800,-1125.56 6800,-1092 6807.72,-1084.28 6946.28,-1084.28 7144.56,-886 8067.44,-886 8216.49,-1035.05 cw(c8212.67,-1038.87) 8216.49,-1042.69 8199.38,-1059.8 ccw(c8203.2,-1063.62) 8199.38,-1067.43 8200.23,-1068.28 ccw(c8204.05,-1064.46) 8207.87,-1068.28 8224.98,-1051.17 cw(c8228.8,-1054.99) 8232.61,-1051.17 8248.03,-1066.59 8248.03,-1075.6 ccw(c8253.43,-1075.6) 8253.43,-1081 8260.21,-1081 cw(c8260.21,-1086.4) 8265.61,-1086.4 8265.61,-1087.6 cw(c8260.21,-1087.6) 8260.21,-1093 8218.43,-1093 ccw(c8218.43,-1098.4) 8213.03,-1098.4 8213.03,-1099.6 ccw(c8218.43,-1099.6) 8218.43,-1105 8242.63,-1105 cw(c8242.63,-1110.4) 8248.03,-1110.4 J4.8@8248.03,-1141.73
A_MX2_N: J4.5 T1.19 | length 2452.4
  Top w6: T1.19@6310.79,-1165.76 6310.79,-1195.79 6331,-1216 6331,-1227.56 6343.44,-1240 6865.56,-1240 7175.56,-930 8030,-930 8131,-1031 8131,-1054.6 cw(c8125.6,-1054.6) 8125.6,-1060 8081.4,-1060 ccw(c8081.4,-1065.4) 8076,-1065.4 8076,-1066.6 ccw(c8081.4,-1066.6) 8081.4,-1072 8125.6,-1072 cw(c8125.6,-1077.4) 8131,-1077.4 8131,-1078.6 cw(c8125.6,-1078.6) 8125.6,-1084 8081.4,-1084 ccw(c8081.4,-1089.4) 8076,-1089.4 8076,-1090.6 ccw(c8081.4,-1090.6) 8081.4,-1096 8125.6,-1096 cw(c8125.6,-1101.4) 8131,-1101.4 8131,-1182.18 J4.5@8169.29,-1220.47
A_MX2_P: J4.6 T1.20 | length 2471.4
  Top w6: T1.20@6360.79,-1165.76 6360.79,-1194.21 6342,-1213 6342,-1223 6348,-1229 6600.6,-1229 ccw(c6600.6,-1223.6) 6606,-1223.6 6606,-1204.4 cw(c6611.4,-1204.4) 6611.4,-1199 6612.6,-1199 cw(c6612.6,-1204.4) 6618,-1204.4 6618,-1223.6 ccw(c6623.4,-1223.6) 6623.4,-1229 6624.6,-1229 ccw(c6624.6,-1223.6) 6630,-1223.6 6630,-1204.4 cw(c6635.4,-1204.4) 6635.4,-1199 6636.6,-1199 cw(c6636.6,-1204.4) 6642,-1204.4 6642,-1223.6 ccw(c6647.4,-1223.6) 6647.4,-1229 6648.6,-1229 ccw(c6648.6,-1223.6) 6654,-1223.6 6654,-1204.4 cw(c6659.4,-1204.4) 6659.4,-1199 6660.6,-1199 cw(c6660.6,-1204.4) 6666,-1204.4 6666,-1223.6 ccw(c6671.4,-1223.6) 6671.4,-1229 6672.6,-1229 ccw(c6672.6,-1223.6) 6678,-1223.6 6678,-1204.4 cw(c6683.4,-1204.4) 6683.4,-1199 6684.6,-1199 cw(c6684.6,-1204.4) 6690,-1204.4 6690,-1223.6 ccw(c6695.4,-1223.6) 6695.4,-1229 6861,-1229 7171,-919 8034.56,-919 8142,-1026.44 8142,-1045.6 ccw(c8147.4,-1045.6) 8147.4,-1051 8166.6,-1051 cw(c8166.6,-1056.4) 8172,-1056.4 8172,-1057.6 cw(c8166.6,-1057.6) 8166.6,-1063 8147.4,-1063 ccw(c8147.4,-1068.4) 8142,-1068.4 8142,-1069.6 ccw(c8147.4,-1069.6) 8147.4,-1075 8166.6,-1075 cw(c8166.6,-1080.4) 8172,-1080.4 8172,-1081.6 cw(c8166.6,-1081.6) 8166.6,-1087 8147.4,-1087 ccw(c8147.4,-1092.4) 8142,-1092.4 8142,-1114.44 J4.6@8169.29,-1141.73
A_MX3_N: J4.1 T1.16 | length 2442.1
  Top w6: T1.16@6160.79,-1165.76 6160.79,-1195.79 6180,-1215 6180,-1262.56 6192.44,-1275 6900.56,-1275 7205.56,-970 7963,-970 7978,-985 7978,-1063.6 cw(c7972.6,-1063.6) 7972.6,-1069 7953.4,-1069 ccw(c7953.4,-1074.4) 7948,-1074.4 7948,-1075.6 ccw(c7953.4,-1075.6) 7953.4,-1081 7972.6,-1081 cw(c7972.6,-1086.4) 7978,-1086.4 7978,-1087.6 cw(c7972.6,-1087.6) 7972.6,-1093 7953.4,-1093 ccw(c7953.4,-1098.4) 7948,-1098.4 7948,-1099.6 ccw(c7953.4,-1099.6) 7953.4,-1105 7972.6,-1105 cw(c7972.6,-1110.4) 7978,-1110.4 7978,-1111.6 cw(c7972.6,-1111.6) 7972.6,-1117 7953.4,-1117 ccw(c7953.4,-1122.4) 7948,-1122.4 7948,-1123.6 ccw(c7953.4,-1123.6) 7953.4,-1129 7972.6,-1129 cw(c7972.6,-1134.4) 7978,-1134.4 7978,-1186.66 J4.1@8011.81,-1220.47
A_MX3_P: J4.2 T1.17 | length 2451.2
  Top w6: T1.17@6210.79,-1165.76 6210.79,-1200.21 6191,-1220 6191,-1258 6197,-1264 6896,-1264 7201,-959 7969,-959 8011.81,-1001.81 8011.81,-1020.6 ccw(c8017.21,-1020.6) 8017.21,-1026 8036.41,-1026 cw(c8036.41,-1031.4) 8041.81,-1031.4 8041.81,-1032.6 cw(c8036.41,-1032.6) 8036.41,-1038 7994.4,-1038 ccw(c7994.4,-1043.4) 7989,-1043.4 7989,-1044.6 ccw(c7994.4,-1044.6) 7994.4,-1050 8036.41,-1050 cw(c8036.41,-1055.4) 8041.81,-1055.4 8041.81,-1056.6 cw(c8036.41,-1056.6) 8036.41,-1062 7994.4,-1062 ccw(c7994.4,-1067.4) 7989,-1067.4 7989,-1068.6 ccw(c7994.4,-1068.6) 7994.4,-1074 8036.41,-1074 cw(c8036.41,-1079.4) 8041.81,-1079.4 8041.81,-1080.6 cw(c8036.41,-1080.6) 8036.41,-1086 8017.21,-1086 ccw(c8017.21,-1091.4) 8011.81,-1091.4 J4.2@8011.81,-1141.73
A_MX4_N: J4.3 T1.13 | length 2444.4
  Top w6: T1.13@6010.79,-1200.79 6030,-1220 6030,-1276.56 6065.44,-1312 6933,-1312 7240,-1005 7908.44,-1005 7944.44,-1041 v1(7945,-1041)
  Bottom w6: v1(7945,-1041) 8029,-1041 8054,-1066 8054,-1183.92 J4.3@8090.55,-1220.47
A_MX4_P: J4.4 T1.14 | length 2450
  Top w6: T1.14@6060.79,-1165.76 6060.79,-1199.21 6041,-1219 6041,-1234.6 ccw(c6046.4,-1234.6) 6046.4,-1240 6065.6,-1240 cw(c6065.6,-1245.4) 6071,-1245.4 6071,-1246.6 cw(c6065.6,-1246.6) 6065.6,-1252 6046.4,-1252 ccw(c6046.4,-1257.4) 6041,-1257.4 6041,-1272 6070,-1301 6928.44,-1301 7235.44,-994 7913,-994 7938,-1019 7949,-1019 v1(7949,-1017)
  Bottom w6: v1(7949,-1017) 7962,-1030 8033.56,-1030 8065,-1061.44 8065,-1116.18 J4.4@8090.55,-1141.73
A_TD1_N: C25.2 T1.3 U1.10 | length 1285.3
  Top w8: U1.10@5630.76,-719.09 5659.29,-719.09 5745,-633.38 5745,-500 5875,-370 6351.62,-370 6420.53,-438.92 cw(c6415.44,-444.01) 6420.53,-449.1 6410.34,-459.29 ccw(c6415.44,-464.38) 6410.34,-469.47 6411.48,-470.6 ccw(c6416.57,-465.51) 6421.66,-470.6 6431.85,-460.41 cw(c6436.94,-465.5) 6442.03,-460.41 6460,-478.38 6460,-535.05 T1.3@6460.79,-535.84 v1@6460.79,-589.21
  Bottom w8: v1(6455,-595) 6460,-590 C25.2@6460,-565
A_TD1_P: C26.2 T1.2 U1.11 | length 1279.9
  Top w8: U1.11@5630.76,-703.34 5656.66,-703.34 5732,-628 5732,-494.62 5869.62,-357 6357,-357 6510.79,-510.79 T1.2@6510.79,-535.84 6510.79,-594.21 v1(6510,-595)
  Bottom w8: v1(6510,-595) C26.2@6510,-565
A_TD2_N: C24.2 T1.6 U1.7 | length 1267.4
  Top w8: U1.7@5630.76,-766.34 5692.04,-766.34 5718,-740.38 5718,-725.38 5722.88,-720.5 5737.88,-720.5 5763,-695.38 5763,-680 5770,-673 5820.38,-673 5835,-658.38 5835,-595 5850,-580 5850,-551.62 5810,-511.62 5810,-498.38 5829.19,-479.19 5845.81,-479.19 5865.74,-459.26 5865.74,-442.65 5898.38,-410 6200,-410 6240,-450 6270,-450 6310,-410 6336.62,-410 6352,-425.38 6352,-449.62 6330,-471.62 6330,-490.79 T1.6@6310.79,-510 ; v1@6310.79,-594.21 T1.6@6310.79,-535.84
  Bottom w8: v1(6310,-595) C24.2@6310,-565
A_TD2_P: C19.2 T1.5 U1.8 | length 1288.6
  Top w8: U1.8@5630.76,-750.59 5689.41,-750.59 5705,-735 5705,-720 5717.5,-707.5 5732.5,-707.5 5750,-690 5750,-670 5760,-660 5815,-660 5822,-653 5822,-589.62 5837,-574.62 5837,-557 5797,-517 5797,-493 5893,-397 6205.38,-397 6245.38,-437 6264.62,-437 6304.62,-397 6342,-397 6365,-420 6365,-455 6345,-475 6345,-490 6360.79,-505.79 T1.5@6360.79,-520 ; v1@6360.79,-594.21 T1.5@6360.79,-535.84
  Bottom w8: v1(6360,-595) C19.2@6360,-565
A_TD3_N: C18.2 T1.9 U1.4 | length 1281.5
  Top w8: U1.4@5630.76,-813.58 5891.42,-813.58 5905,-800 5905,-770 5887,-752 5800.38,-752 5791.69,-743.31 5791.69,-736.69 5808.38,-720 5885,-720 5898,-707 5898,-663 5878,-643 5878,-620.38 5898,-600.38 5898,-492 5940,-450 6075,-450 6095,-470 6130,-470 6150,-450 6165,-450 6180,-465 6180,-485.79 6160.79,-505 T1.9@6160.79,-535.84 6160.79,-594.21 v1(6160,-595)
  Bottom w8: v1(6160,-595) C18.2@6160,-565
A_TD3_P: C23.2 T1.8 U1.5 | length 1280.9
  Top w8: U1.5@5630.76,-797.83 5882.17,-797.83 5892,-788 5892,-775.38 5881.62,-765 5795,-765 5778.69,-748.69 5778.69,-731.31 5803,-707 5878,-707 5885,-700 5885,-670 5865,-650 5865,-615 5885,-595 5885,-486.62 5934.62,-437 6172,-437 6195,-460 6195,-490 6210.79,-505.79 T1.8@6210.79,-535.84 6210.79,-594.21 v1(6210,-595)
  Bottom w8: v1(6210,-595) C23.2@6210,-565
A_TD4_N: C21.2 T1.12 U1.1 | length 1289.2
  Top w8: U1.1@5630.76,-860.82 5665.82,-860.82 5680,-875 5740,-875 5740.37,-875.37 6028.01,-875.37 6048,-855.38 6048,-794.62 6033.38,-780 5970,-780 5958,-768 5958,-735 5968,-725 6015,-725 6030,-710 6030,-675 6017,-662 5962,-662 5958,-658 5958,-642 5965,-635 6020,-635 6025,-630 6025,-620 6020,-615 5965,-615 5958,-608 5958,-500.38 5970.38,-488 6000,-488 6010.79,-498.79 T1.12@6010.79,-535.84 6010,-536.63 v1(6010,-595)
  Bottom w8: v1(6010,-595) C21.2@6010,-565
A_TD4_P: C22.2 T1.11 U1.2 | length 1294.1
  Top w8: U1.2@5630.76,-845.08 5668.47,-845.08 5685.38,-862 5725.8,-862 ccw(c5725.8,-854.8) 5733,-854.8 5733,-833.78 cw(c5740.2,-833.78) 5740.2,-826.58 5741.8,-826.58 cw(c5741.8,-833.78) 5749,-833.78 5749,-856 ccw(c5755,-856) 5755,-862 6023,-862 6035,-850 6035,-800 6028,-793 5964.62,-793 5945,-773.38 5945,-729.62 5962.62,-712 6009.62,-712 6017,-704.62 6017,-682 6010,-675 5951.62,-675 5945,-668.38 5945,-495 5965,-475 6050,-475 6060.79,-485.79 T1.11@6060.79,-535.84 6060,-536.63 v1(6060,-595)
  Bottom w8: v1(6060,-595) C22.2@6060,-565
APHY105: B2.1 C8.1 C9.1 C10.1 U1.3 U1.9 U1.40 | length 766.5
  Top w8: v1(5466.43,-950) 5476.43,-940 U1.40@5476.43,-889.17 ; U1.3@5630.76,-829.33 5684.33,-829.33 v1(5695,-840) ; U1.9@5630.76,-734.84 5670.16,-734.84 v1(5685,-720)
  Top w18: v1(5695,-930) B2.1@5730.47,-930
  Bottom w12: v1(5466.43,-950) 5475,-941.43 C10.1@5475,-930 ; C10.1@5475,-919.53 C10.1@5475,-930 ; v1(5685,-720) C8.1@5725.47,-720 ; v1(5695,-930) C10.1@5475,-930 ; v1(5695,-840) 5705,-830 C9.1@5730.47,-830
  Bottom w15: v1(5695,-930) v1(5695,-840) ; C8.1@5725.47,-720 5731.5,-726.03 5731.5,-828.97 C9.1@5730.47,-830
B3V3A: B6.1 C48.1 C49.1 C50.1 U4.6 U4.41 | length 673.4
  Top w8: U4.41@1462.18,-944.17 1462.18,-996.72 1463,-997.54 1463,-998 v1(1470,-1005) ; U4.6@1600.76,-837.08 1657.08,-837.08 v1(1660,-840)
  Top w15: v1(1620,-940) 1620,-985 v1(1635,-1000)
  Bottom w15: C49.1@1470,-1050.47 v1(1470,-1005) 1475,-1000 v1(1635,-1000) ; v1(1620,-940) 1629.53,-930.47 C48.1@1629.53,-840 ; C48.1@1625,-837.08 1627.92,-840 C48.1@1629.53,-840 ; v1(1660,-840) C48.1@1629.53,-840
  Bottom w18: B6.1@1340,-1050.47 C50.1@1410,-1050.47 C49.1@1470,-1050.47
B3V3D: B4.2 B6.2 C38.1 C39.1 C40.1 C41.1 C62.1 C63.1 R71.1 R74.1 R79.1 R83.2 R84.1 R85.2 R87.2 R89.2 R90.2 R91.2 R96.2 R100.2 R102.2 R105.2 R108.2 R200.2 R201.2 R312.2 R313.2 R314.2 U4.15 U4.21 U4.37 U5.2 U5.4 | length 7423.7
  Top w8: v1(1430,-655) 1446.43,-671.43 U4.21@1446.43,-714.25 ; U4.15@1540.92,-714.25 v1@1540.92,-655
  Top w10: R85.2@1385,-1080 1380,-1080 1345,-1045 v1(1345,-975) 1385,-975 1399.19,-960.81 U4.37@1399.19,-944.17
  Top w12: v1(905,-545) 925,-565 1045,-565 v2(1045,-555) ; v1(1015,-635) R71.1@1045,-635 R90.2@1045,-680 ; v1(1020,-920) R87.2@1045,-920 ; v1(1020,-820) 1045,-820 ; R100.2@1045,-840 1045,-820 ; R91.2@1045,-800 1045,-820 ; R83.2@1310,-545 v1(1310,-425) ; v1(1340,-1280) 3157.09,-1280 v1@3158.54,-1281.46 ; R108.2@1355,-450 v1(1355,-425) ; v1(1495,-425) R105.2@1495,-450 R102.2@1540,-450 ; R96.2@1630,-450 v1(1630,-425) ; v1(1815,-425) 1995,-425 2210,-210 v1(2545,-210) ; v1(3160,-1230) R89.2@3215,-1230 ; v1(3160,-1185) 3160,-1170 3180,-1150 R74.1@3215,-1150 ; v1(3290,-1230) R79.1@3315,-1230
  Top w15: v2(1275,-555) 1275,-595 1335,-655 v1(1430,-655) ; v1(1375,-1105) 1385,-1095 R85.2@1385,-1080
  Top w18: C63.1@940,-1140.47 940.47,-1140 C62.1@1000,-1140 1120,-1140 1153,-1173 v1(1340,-1173) 1360,-1173 1372,-1185 B4.2@1385.47,-1185
  Top w24: C63.1@940,-1140.47 C40.1@940,-1080 960,-1080 995,-1045 v2(995,-1020) ; v2(1045,-555) v2(1160,-555) ; v2(1275,-555) 1285,-545 R83.2@1310,-545
  Top w30: R84.1@515,-1090 U5.2@605,-1090 ; U5.4@855,-1090 855,-1135 860.47,-1140.47 C63.1@940,-1140.47
  Bottom w8: C39.1@1440,-675.47 C39.1@1445,-680.47
  Bottom w10: B6.2@1330,-1110 1339.53,-1110 B6.2@1340,-1109.53 ; C38.1@1540.8,-679.68 1545,-675.48 v1(1545,-655)
  Bottom w12: R314.2@530,-475 R313.2@570,-475 570,-525 589.11,-544.11 670,-544.11 ; R312.2@670,-475 670,-544.11 ; v1(905,-545) 904.11,-544.11 670,-544.11 ; v1(1015,-635) 1045,-635 ; v1(1020,-920) 1045,-920 ; v1(1020,-820) 1045,-820 ; v1(1310,-425) v1(1355,-425) v1(1495,-425) v1(1630,-425) v1(1815,-425) ; v1(2545,-210) R200.2@2545,-90 R201.2@2545,-40 ; v1(3160,-1280) v1(3160,-1230) ; v1(3160,-1185) v1(3160,-1230) ; v1(3290,-1230) v1(3160,-1230)
  Bottom w15: B6.2@1339.53,-1110 B6.2@1340,-1110 ; v1(1340,-1280) v1(1340,-1173) B6.2@1340,-1110 ; B6.2@1340,-1109.53 B6.2@1340,-1110 ; v1@1345,-974.53 C41.1@1375,-974.53 ; v1(1375,-1105) 1370,-1110 B6.2@1340,-1110 ; v1(1430,-655) 1446.43,-671.43 C39.1@1446.43,-679.68 ; C39.1@1445,-680.47 1445.79,-679.68 C39.1@1446.43,-679.68 ; C39.1@1446.43,-680 C39.1@1446.43,-679.68 ; C38.1@1540.8,-679.68 C39.1@1446.43,-679.68
  Bottom w24: v2(995,-1020) 1045,-970 1045,-920 1045,-820 1045,-635 v2(1045,-555) ; v2(1160,-555) v2(1275,-555)
B5V: C64.1 C65.1 Q6.3 R84.2 R86.1 U5.3 | length 440.3
  Top w32: R86.1@245,-1150 285,-1190 Q6.3@350,-1190 455,-1190 495,-1190 504,-1181 515,-1181 ; C64.1@515,-1210 515,-1181 ; R84.2@515,-1150 515,-1181 ; U5.3@605,-1181 515,-1181
B_MCLK: JP2.A3 R97.1 | length 880.9
  Top w5: JP2.A3@709.84,-115.35 710.35,-115.35 755,-160 755,-664.14 810.86,-720 R97.1@1045,-720
B_MDIO: JP2.A4 R99.1 | length 922.2
  Top w5: JP2.A4@809.84,-115.35 765,-160.2 765,-660 815,-710 1005,-710 1010,-705 v1(1010,-700) ; v1(1010,-745) 1025,-760 R99.1@1045,-760
  Bottom w5: v1(1010,-745) v1(1010,-700)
